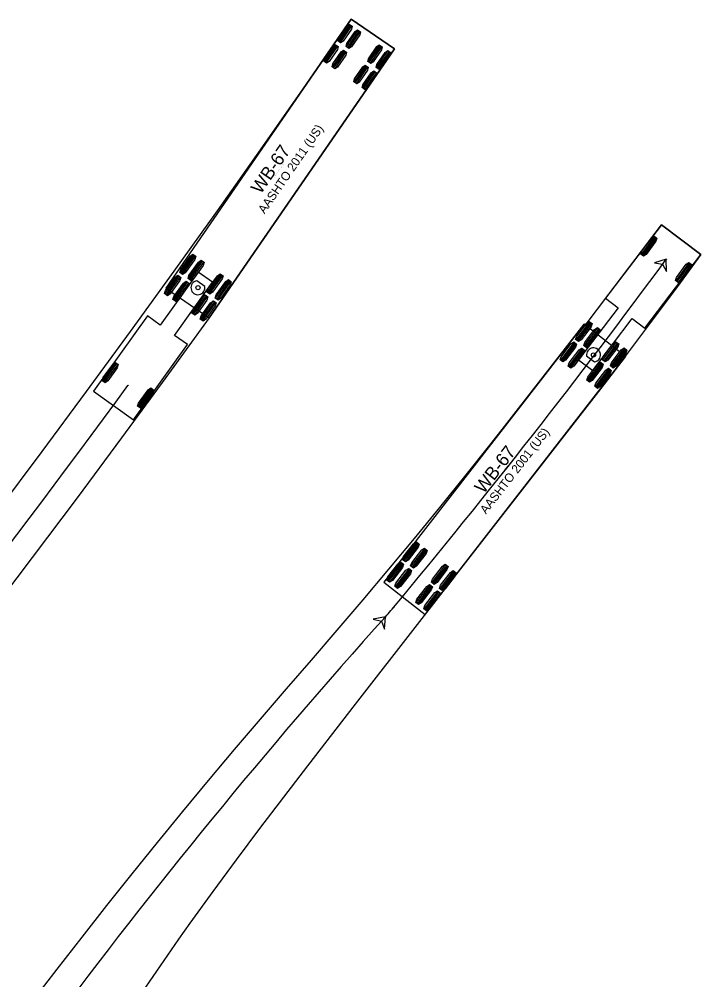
# Model space of a CAD drawing. Extents: x 2175591 to 2194071, y 76570 to 86955.
# Drawn here: x 2176657.4 to 2176768, y 77434.5 to 77590.4 of the extents above; entities that cross this region are included whole.
import ezdxf

# ---------------------------------------------------------------- set-up
doc = ezdxf.new("R2010")
doc.units = 0
doc.layers.add('C-UTIL-STRM-TEXT', color=7, linetype='Continuous')

msp = doc.modelspace()

# ---------------------------------------------------------------- linework, layer by layer
at = {"layer": 'C-UTIL-STRM-TEXT'}
for p, q in [((2176711.25, 77590.38), (2176681.16, 77546.75)), ((2176718.25, 77585.55), (2176711.25, 77590.38)), ((2176709.08, 77586.83), (2176710.96, 77589.55)), ((2176709.27, 77586.7), (2176711.14, 77589.42)), ((2176709.46, 77586.57), (2176711.33, 77589.29)), ((2176710.44, 77585.9), (2176712.31, 77588.61)), ((2176710.63, 77585.76), (2176712.5, 77588.48)), ((2176710.82, 77585.63), (2176712.69, 77588.35)), ((2176688.16, 77541.92), (2176718.25, 77585.55)), ((2176706.81, 77583.54), (2176708.69, 77586.26)), ((2176707, 77583.41), (2176708.87, 77586.13)), ((2176707.19, 77583.28), (2176709.06, 77586)), ((2176708.17, 77582.6), (2176710.04, 77585.32)), ((2176708.36, 77582.47), (2176710.23, 77585.19)), ((2176708.55, 77582.34), (2176710.42, 77585.06)), ((2176713.97, 77583.46), (2176715.84, 77586.18)), ((2176714.16, 77583.33), (2176716.03, 77586.05)), ((2176714.34, 77583.2), (2176716.22, 77585.92)), ((2176715.33, 77582.53), (2176717.2, 77585.24)), ((2176715.51, 77582.4), (2176717.39, 77585.11)), ((2176715.7, 77582.27), (2176717.58, 77584.98)), ((2176711.7, 77580.17), (2176713.57, 77582.89)), ((2176711.89, 77580.04), (2176713.76, 77582.76)), ((2176712.07, 77579.91), (2176713.95, 77582.63)), ((2176713.06, 77579.23), (2176714.93, 77581.95)), ((2176713.24, 77579.1), (2176715.12, 77581.82)), ((2176713.43, 77578.97), (2176715.31, 77581.69)), ((2176761.59, 77557.01), (2176752.51, 77545.08)), ((2176767.96, 77552.17), (2176761.59, 77557.01)), ((2176761.59, 77557.01), (2176761.59, 77557.01)), ((2176760.43, 77555.16), (2176758.26, 77552.2)), ((2176760.61, 77555.02), (2176758.44, 77552.07)), ((2176760.8, 77554.89), (2176758.63, 77551.93)), ((2176683.45, 77549.22), (2176685.59, 77552.2)), ((2176683.64, 77549.08), (2176685.78, 77552.06)), ((2176683.83, 77548.95), (2176685.96, 77551.93)), ((2176684.8, 77548.26), (2176686.93, 77551.24)), ((2176684.98, 77548.12), (2176687.12, 77551.1)), ((2176685.17, 77547.99), (2176687.3, 77550.97)), ((2176758.87, 77540.23), (2176767.96, 77552.17)), ((2176766.08, 77550.88), (2176763.9, 77547.93)), ((2176766.26, 77550.74), (2176764.09, 77547.79)), ((2176766.44, 77550.61), (2176764.27, 77547.65)), ((2176686.42, 77549.35), (2176680.25, 77540.73)), ((2176688.75, 77547.68), (2176686.42, 77549.35)), ((2176681.01, 77545.8), (2176683.14, 77548.78)), ((2176681.19, 77545.67), (2176683.33, 77548.65)), ((2176681.38, 77545.54), (2176683.52, 77548.52)), ((2176682.35, 77544.84), (2176684.48, 77547.82)), ((2176682.54, 77544.71), (2176684.67, 77547.69)), ((2176682.58, 77539.06), (2176688.75, 77547.68)), ((2176682.72, 77544.57), (2176684.86, 77547.56)), ((2176687.49, 77546.99), (2176686.18, 77547.93)), ((2176687.87, 77546.05), (2176690.01, 77549.03)), ((2176688.06, 77545.92), (2176690.19, 77548.9)), ((2176688.24, 77545.79), (2176690.38, 77548.77)), ((2176689.21, 77545.09), (2176691.35, 77548.07)), ((2176689.4, 77544.96), (2176691.53, 77547.94)), ((2176689.58, 77544.82), (2176691.72, 77547.81)), ((2176681.16, 77546.75), (2176688.16, 77541.92)), ((2176685.43, 77542.64), (2176687.56, 77545.62)), ((2176685.61, 77542.5), (2176687.75, 77545.49)), ((2176685.8, 77542.37), (2176687.93, 77545.35)), ((2176686.77, 77541.68), (2176688.9, 77544.66)), ((2176686.95, 77541.54), (2176689.09, 77544.52)), ((2176687.14, 77541.41), (2176689.27, 77544.39)), ((2176752.51, 77545.08), (2176754.55, 77543.52)), ((2176754.55, 77543.52), (2176748.14, 77535.1)), ((2176678.16, 77542.22), (2176669.43, 77530.03)), ((2176680.25, 77540.73), (2176678.16, 77542.22)), ((2176688.16, 77541.92), (2176688.16, 77541.92)), ((2176749.91, 77541.29), (2176747.69, 77538.37)), ((2176750.42, 77533.36), (2176756.83, 77541.79)), ((2176756.83, 77541.79), (2176758.87, 77540.23)), ((2176749.02, 77540.87), (2176716.52, 77499)), ((2176750.09, 77541.15), (2176747.87, 77538.23)), ((2176750.28, 77541.01), (2176748.06, 77538.1)), ((2176751.22, 77540.29), (2176749, 77537.37)), ((2176755.74, 77535.65), (2176749.02, 77540.87)), ((2176749.02, 77540.87), (2176749.02, 77540.87)), ((2176751.41, 77540.15), (2176749.19, 77537.24)), ((2176751.59, 77540.01), (2176749.37, 77537.1)), ((2176684.67, 77537.56), (2176682.58, 77539.06)), ((2176675.93, 77525.37), (2176684.67, 77537.56)), ((2176747.39, 77537.98), (2176745.17, 77535.06)), ((2176747.57, 77537.84), (2176745.35, 77534.92)), ((2176747.75, 77537.7), (2176745.53, 77534.78)), ((2176748.7, 77536.98), (2176746.48, 77534.06)), ((2176748.88, 77536.84), (2176746.66, 77533.92)), ((2176749.07, 77536.7), (2176746.84, 77533.78)), ((2176754.23, 77538), (2176752.01, 77535.08)), ((2176754.42, 77537.86), (2176752.2, 77534.94)), ((2176754.6, 77537.72), (2176752.38, 77534.8)), ((2176755.55, 77537), (2176753.33, 77534.08)), ((2176755.73, 77536.86), (2176753.51, 77533.94)), ((2176755.91, 77536.72), (2176753.69, 77533.81)), ((2176723.23, 77493.79), (2176755.74, 77535.65)), ((2176748.14, 77535.1), (2176750.42, 77533.36)), ((2176749.41, 77535.74), (2176750.69, 77534.76)), ((2176670.86, 77531.67), (2176673.03, 77534.63)), ((2176671.05, 77531.54), (2176673.21, 77534.5)), ((2176671.23, 77531.4), (2176673.4, 77534.36)), ((2176751.71, 77534.68), (2176749.49, 77531.77)), ((2176751.89, 77534.55), (2176749.67, 77531.63)), ((2176752.08, 77534.41), (2176749.85, 77531.49)), ((2176753.02, 77533.68), (2176750.8, 77530.77)), ((2176753.21, 77533.55), (2176750.98, 77530.63)), ((2176753.39, 77533.41), (2176751.17, 77530.49)), ((2176676.62, 77527.54), (2176678.78, 77530.5)), ((2176676.8, 77527.41), (2176678.97, 77530.37)), ((2176669.43, 77530.03), (2176675.93, 77525.37)), ((2176676.99, 77527.27), (2176679.15, 77530.23)), ((2176675.93, 77525.37), (2176675.93, 77525.37)), ((2176721.86, 77505.51), (2176719.61, 77502.62)), ((2176722.04, 77505.37), (2176719.79, 77502.48)), ((2176722.22, 77505.23), (2176719.97, 77502.34)), ((2176723.16, 77504.5), (2176720.91, 77501.6)), ((2176723.34, 77504.36), (2176721.1, 77501.46)), ((2176723.52, 77504.22), (2176721.28, 77501.32)), ((2176719.3, 77502.22), (2176717.06, 77499.33)), ((2176719.49, 77502.08), (2176717.24, 77499.18)), ((2176719.67, 77501.94), (2176717.42, 77499.04)), ((2176720.61, 77501.21), (2176718.36, 77498.31)), ((2176720.79, 77501.07), (2176718.54, 77498.17)), ((2176720.97, 77500.93), (2176718.72, 77498.03)), ((2176726.55, 77501.87), (2176724.3, 77498.98)), ((2176726.73, 77501.73), (2176724.48, 77498.84)), ((2176726.91, 77501.59), (2176724.66, 77498.7)), ((2176727.85, 77500.86), (2176725.6, 77497.97)), ((2176728.03, 77500.72), (2176725.78, 77497.82)), ((2176728.21, 77500.58), (2176725.96, 77497.68)), ((2176716.52, 77499), (2176723.23, 77493.79)), ((2176723.99, 77498.58), (2176721.74, 77495.69)), ((2176724.17, 77498.44), (2176721.92, 77495.55)), ((2176724.35, 77498.3), (2176722.1, 77495.41)), ((2176725.29, 77497.57), (2176723.05, 77494.67)), ((2176725.47, 77497.43), (2176723.23, 77494.53)), ((2176725.66, 77497.29), (2176723.41, 77494.39))]:
    msp.add_line(p, q, dxfattribs=at)
for points in [[(2176582.54, 77421.04), (2176616.93, 77463.27), (2176620.72, 77467.96), (2176624.48, 77472.67), (2176628.23, 77477.39), (2176631.96, 77482.13), (2176639.21, 77491.43), (2176646.53, 77500.95), (2176653.84, 77510.57), (2176661.09, 77520.23), (2176668.29, 77529.94), (2176675.42, 77539.68), (2176682.51, 77549.47), (2176689.53, 77559.3), (2176696.51, 77569.17), (2176703.43, 77579.07), (2176711.25, 77590.38), (2176718.25, 77585.55), (2176718.16, 77585.42), (2176718.16, 77585.42)], [(2176718.16, 77585.42), (2176688.16, 77541.92), (2176681.15, 77532.22), (2176673.98, 77522.43), (2176666.76, 77512.69), (2176659.47, 77502.99), (2176652.12, 77493.33), (2176644.76, 77483.77), (2176637.47, 77474.42), (2176629.96, 77464.91), (2176622.39, 77455.44), (2176618.58, 77450.74), (2176614.82, 77446.13), (2176611.1, 77441.62), (2176607.44, 77437.21), (2176603.2, 77432.15)], [(2176659.54, 77431.01), (2176663.53, 77436.22), (2176667.55, 77441.4), (2176671.59, 77446.55), (2176675.67, 77451.67), (2176679.78, 77456.76), (2176683.91, 77461.81), (2176688.07, 77466.84), (2176692.27, 77471.84), (2176696.49, 77476.8), (2176700.71, 77481.71), (2176704.78, 77486.38), (2176708.96, 77491.22), (2176713.17, 77496.16), (2176717.35, 77501.12), (2176721.49, 77506.11), (2176725.61, 77511.13), (2176729.69, 77516.17), (2176733.75, 77521.23), (2176735.75, 77523.77), (2176749.02, 77540.87), (2176749.36, 77540.9), (2176753.01, 77545.74), (2176761.59, 77557.01), (2176767.96, 77552.17), (2176764.18, 77547.02), (2176760.3, 77541.8), (2176755.9, 77535.95), (2176755.69, 77535.59), (2176751.74, 77530.42), (2176711.87, 77479.21), (2176704.12, 77469.2), (2176700.23, 77464.12), (2176696.37, 77459.03), (2176692.54, 77453.93), (2176688.76, 77448.81), (2176685.05, 77443.66), (2176683.21, 77441.07), (2176681.4, 77438.47), (2176679.61, 77435.87), (2176677.85, 77433.26)], [(2176716.79, 77493.4), (2176717.01, 77493.65), (2176717.23, 77493.9), (2176717.45, 77494.15), (2176717.67, 77494.4), (2176717.89, 77494.65), (2176718.1, 77494.91)]]:
    msp.add_lwpolyline(points, dxfattribs=at)
for points in [[(2176709.51, 77586.54), (2176709.04, 77586.86), (2176709.16, 77587.34), (2176710.51, 77589.3), (2176710.91, 77589.58), (2176711.38, 77589.26), (2176711.26, 77588.78), (2176709.91, 77586.82)], [(2176710.87, 77585.6), (2176710.39, 77585.93), (2176710.51, 77586.41), (2176711.86, 77588.36), (2176712.27, 77588.64), (2176712.74, 77588.32), (2176712.62, 77587.84), (2176711.27, 77585.89)], [(2176707.24, 77583.25), (2176706.77, 77583.57), (2176706.89, 77584.05), (2176708.23, 77586.01), (2176708.64, 77586.29), (2176709.11, 77585.96), (2176708.99, 77585.48), (2176707.64, 77583.53)], [(2176708.59, 77582.31), (2176708.12, 77582.63), (2176708.24, 77583.11), (2176709.59, 77585.07), (2176710, 77585.35), (2176710.47, 77585.03), (2176710.35, 77584.55), (2176709, 77582.59)], [(2176714.39, 77583.17), (2176713.92, 77583.5), (2176714.04, 77583.97), (2176715.39, 77585.93), (2176715.79, 77586.21), (2176716.26, 77585.89), (2176716.14, 77585.41), (2176714.8, 77583.45)], [(2176715.75, 77582.23), (2176715.28, 77582.56), (2176715.4, 77583.04), (2176716.75, 77584.99), (2176717.15, 77585.28), (2176717.62, 77584.95), (2176717.5, 77584.47), (2176716.15, 77582.52)], [(2176712.12, 77579.88), (2176711.65, 77580.2), (2176711.77, 77580.68), (2176713.12, 77582.64), (2176713.52, 77582.92), (2176713.99, 77582.59), (2176713.87, 77582.12), (2176712.52, 77580.16)], [(2176713.48, 77578.94), (2176713.01, 77579.27), (2176713.13, 77579.74), (2176714.48, 77581.7), (2176714.88, 77581.98), (2176715.35, 77581.66), (2176715.23, 77581.18), (2176713.88, 77579.22)], [(2176760.38, 77555.19), (2176760.84, 77554.85), (2176760.68, 77554.34), (2176759.12, 77552.21), (2176758.67, 77551.9), (2176758.21, 77552.24), (2176758.38, 77552.75), (2176759.94, 77554.88)], [(2176683.87, 77548.92), (2176683.41, 77549.25), (2176683.57, 77549.77), (2176685.1, 77551.91), (2176685.54, 77552.23), (2176686.01, 77551.9), (2176685.85, 77551.38), (2176684.31, 77549.23)], [(2176685.21, 77547.96), (2176684.75, 77548.29), (2176684.91, 77548.81), (2176686.45, 77550.95), (2176686.88, 77551.27), (2176687.35, 77550.94), (2176687.19, 77550.42), (2176685.65, 77548.27)], [(2176762.35, 77551.41), (2176760.43, 77550.85), (2176761.76, 77550.6), (2176762.39, 77549.41)], [(2176766.03, 77550.91), (2176766.49, 77550.57), (2176766.32, 77550.06), (2176764.76, 77547.93), (2176764.32, 77547.62), (2176763.86, 77547.96), (2176764.02, 77548.47), (2176765.59, 77550.6)], [(2176688.29, 77545.75), (2176687.82, 77546.09), (2176687.98, 77546.6), (2176689.52, 77548.75), (2176689.96, 77549.07), (2176690.43, 77548.73), (2176690.27, 77548.22), (2176688.73, 77546.07)], [(2176681.43, 77545.5), (2176680.96, 77545.84), (2176681.12, 77546.35), (2176682.66, 77548.5), (2176683.1, 77548.82), (2176683.56, 77548.48), (2176683.4, 77547.97), (2176681.87, 77545.82)], [(2176682.77, 77544.54), (2176682.3, 77544.87), (2176682.46, 77545.39), (2176684, 77547.54), (2176684.44, 77547.86), (2176684.9, 77547.52), (2176684.74, 77547), (2176683.21, 77544.86)], [(2176689.63, 77544.79), (2176689.17, 77545.12), (2176689.32, 77545.64), (2176690.86, 77547.79), (2176691.3, 77548.11), (2176691.77, 77547.77), (2176691.61, 77547.25), (2176690.07, 77545.11)], [(2176685.84, 77542.34), (2176685.38, 77542.67), (2176685.54, 77543.19), (2176687.08, 77545.33), (2176687.51, 77545.65), (2176687.98, 77545.32), (2176687.82, 77544.8), (2176686.28, 77542.65)], [(2176687.19, 77541.38), (2176686.72, 77541.71), (2176686.88, 77542.23), (2176688.42, 77544.37), (2176688.86, 77544.69), (2176689.32, 77544.36), (2176689.16, 77543.84), (2176687.62, 77541.69)], [(2176749.87, 77541.33), (2176750.32, 77540.98), (2176750.15, 77540.47), (2176748.55, 77538.37), (2176748.1, 77538.06), (2176747.65, 77538.41), (2176747.82, 77538.92), (2176749.42, 77541.02)], [(2176751.18, 77540.33), (2176751.63, 77539.98), (2176751.46, 77539.47), (2176749.86, 77537.37), (2176749.41, 77537.06), (2176748.96, 77537.41), (2176749.13, 77537.92), (2176750.73, 77540.02)], [(2176747.34, 77538.01), (2176747.8, 77537.66), (2176747.62, 77537.15), (2176746.02, 77535.05), (2176745.58, 77534.75), (2176745.12, 77535.09), (2176745.3, 77535.61), (2176746.89, 77537.71)], [(2176748.66, 77537.01), (2176749.11, 77536.66), (2176748.94, 77536.15), (2176747.34, 77534.05), (2176746.89, 77533.75), (2176746.43, 77534.09), (2176746.61, 77534.61), (2176748.21, 77536.71)], [(2176754.19, 77538.03), (2176754.64, 77537.69), (2176754.47, 77537.17), (2176752.87, 77535.07), (2176752.42, 77534.77), (2176751.97, 77535.12), (2176752.14, 77535.63), (2176753.74, 77537.73)], [(2176755.5, 77537.03), (2176755.96, 77536.69), (2176755.78, 77536.18), (2176754.18, 77534.07), (2176753.74, 77533.77), (2176753.28, 77534.12), (2176753.45, 77534.63), (2176755.05, 77536.73)], [(2176671.28, 77531.37), (2176670.82, 77531.71), (2176670.98, 77532.22), (2176672.54, 77534.35), (2176672.98, 77534.67), (2176673.44, 77534.33), (2176673.28, 77533.81), (2176671.72, 77531.68)], [(2176751.67, 77534.72), (2176752.12, 77534.37), (2176751.95, 77533.86), (2176750.35, 77531.76), (2176749.9, 77531.45), (2176749.44, 77531.8), (2176749.62, 77532.31), (2176751.22, 77534.41)], [(2176752.98, 77533.72), (2176753.43, 77533.37), (2176753.26, 77532.86), (2176751.66, 77530.76), (2176751.21, 77530.46), (2176750.76, 77530.8), (2176750.93, 77531.31), (2176752.53, 77533.42)], [(2176677.03, 77527.24), (2176676.57, 77527.57), (2176676.74, 77528.09), (2176678.29, 77530.22), (2176678.74, 77530.53), (2176679.2, 77530.2), (2176679.03, 77529.68), (2176677.48, 77527.55)], [(2176721.81, 77505.55), (2176722.27, 77505.2), (2176722.09, 77504.69), (2176720.47, 77502.6), (2176720.02, 77502.3), (2176719.57, 77502.65), (2176719.74, 77503.16), (2176721.36, 77505.25)], [(2176723.12, 77504.54), (2176723.57, 77504.18), (2176723.39, 77503.67), (2176721.77, 77501.59), (2176721.32, 77501.29), (2176720.87, 77501.64), (2176721.05, 77502.15), (2176722.67, 77504.24)], [(2176719.26, 77502.26), (2176719.71, 77501.91), (2176719.53, 77501.39), (2176717.91, 77499.31), (2176717.46, 77499.01), (2176717.01, 77499.36), (2176717.19, 77499.87), (2176718.81, 77501.96)], [(2176720.56, 77501.24), (2176721.01, 77500.89), (2176720.84, 77500.38), (2176719.22, 77498.3), (2176718.77, 77498), (2176718.31, 77498.35), (2176718.49, 77498.86), (2176720.11, 77500.94)], [(2176726.5, 77501.91), (2176726.95, 77501.56), (2176726.77, 77501.05), (2176725.16, 77498.96), (2176724.7, 77498.66), (2176724.25, 77499.01), (2176724.43, 77499.52), (2176726.05, 77501.61)], [(2176727.8, 77500.9), (2176728.26, 77500.55), (2176728.08, 77500.03), (2176726.46, 77497.95), (2176726.01, 77497.65), (2176725.56, 77498), (2176725.73, 77498.51), (2176727.35, 77500.6)], [(2176723.95, 77498.62), (2176724.4, 77498.27), (2176724.22, 77497.76), (2176722.6, 77495.67), (2176722.15, 77495.37), (2176721.7, 77495.72), (2176721.88, 77496.23), (2176723.49, 77498.32)], [(2176725.25, 77497.61), (2176725.7, 77497.25), (2176725.52, 77496.74), (2176723.9, 77494.66), (2176723.45, 77494.36), (2176723, 77494.71), (2176723.18, 77495.22), (2176724.8, 77497.31)], [(2176716.79, 77493.4), (2176714.82, 77493.03), (2176716.12, 77492.66), (2176716.63, 77491.41)]]:
    msp.add_lwpolyline(points, close=True, dxfattribs=at)
for centre, radius in [((2176762.35, 77551.41), 0.0417), ((2176686.36, 77546.8), 0.34), ((2176750.54, 77535.89), 0.34), ((2176675.01, 77530.95), 0.0417), ((2176718.1, 77494.91), 0.0417), ((2176718.1, 77494.91), 0.0417), ((2176716.79, 77493.4), 0.0417), ((2176716.79, 77493.4), 0.0417)]:
    msp.add_circle(centre, radius, dxfattribs=at)
for centre, radius, start, end in [((2175810.3, 78251.48), 1181.73, 320.19177, 323.67175), ((2176686.36, 77546.8), 1.14, 99.3841, 9.3841), ((2176750.54, 77535.89), 1.14, 277.7183, 187.7183), ((2175070.31, 78704.47), 1988.01, 320.72292, 323.82204), ((2177412.9, 76868.12), 935.71, 138.06833, 143.36998)]:
    msp.add_arc(centre, radius, start, end, dxfattribs=at)

# ---------------------------------------------------------------- texts
for s, height, rotation, p in [('AASHTO 2011 (US)', 1.4167, 55.4103, (2176697.17, 77558.71)), ('WB-67', 2.125, 55.4103, (2176696.55, 77561.87)), ('(c) 2019 Transoft Solutions, Inc. All rights reserved.', 0.085, 55.4103, (2176698.76, 77564.7)), ('AASHTO 2001 (US)', 1.4167, 52.1703, (2176733.11, 77509.97)), ('WB-67', 2.125, 52.1703, (2176732.73, 77513.24)), ('(c) 2019 Transoft Solutions, Inc. All rights reserved.', 0.085, 52.1703, (2176735.1, 77515.93))]:
    msp.add_text(s, height=height, rotation=rotation, dxfattribs=at).set_placement(p)

doc.saveas('drawing.dxf')
